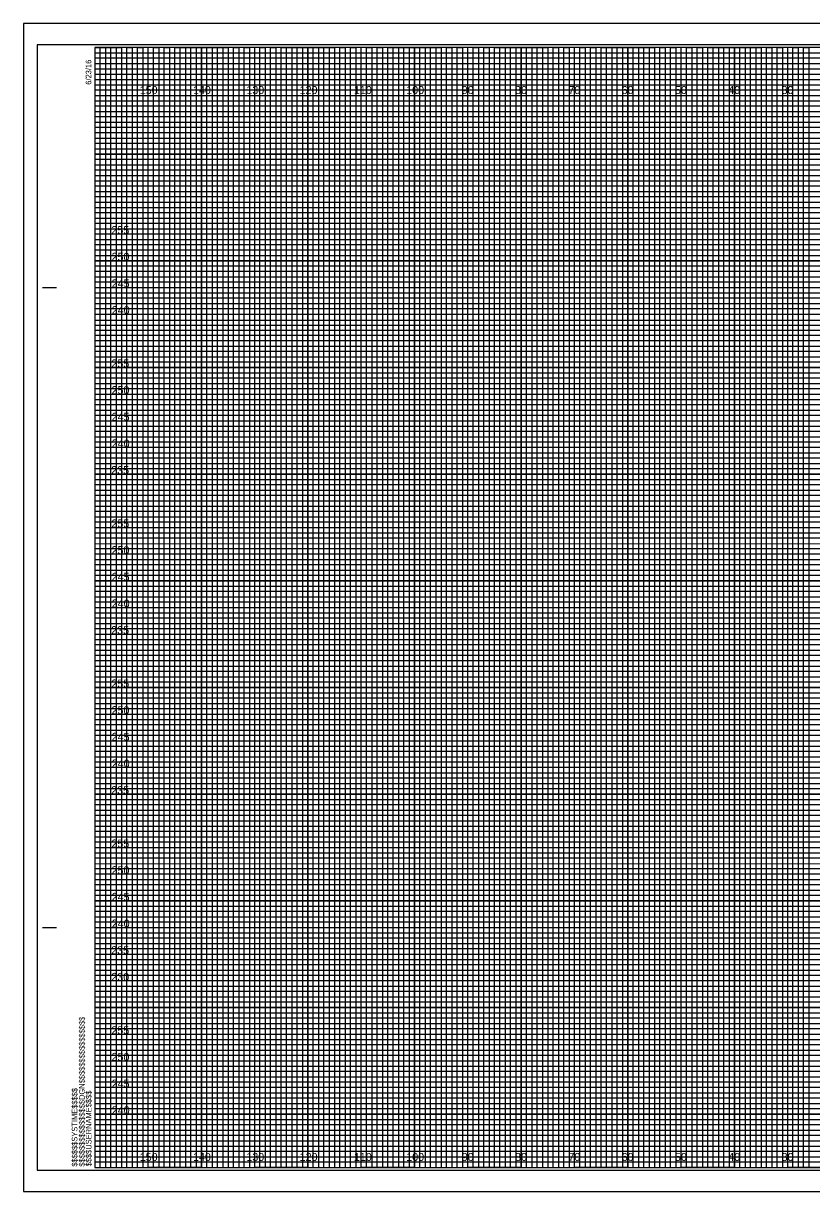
# Model space of a CAD drawing. Extents: x -13 to 323, y -5 to 434.
# Drawn here: x -13.4 to 134.5, y -4.5 to 214.5 of the extents above; entities that cross this region are included whole.
import ezdxf

# ---------------------------------------------------------------- set-up
doc = ezdxf.new("R2010")
doc.units = 0
for name, color, linetype in [('Exist Cross Section Cell', 7, 'Continuous'), ('Exist XS Center Line Elevation Label', 7, 'Continuous'), ('Exist XS Ground Line', 7, 'Continuous'), ('Prop CMT Conc Surface', 7, 'Continuous'), ('Prop CMT Concrete Structures', 7, 'Continuous'), ('Prop CMT DNC', 7, 'Continuous'), ('Prop CMT Pvmt Course 1 Wedge', 7, 'Continuous'), ('Prop CMT Pvmt Course 2', 7, 'Continuous'), ('Prop CMT Pvmt Course 2 Wedge', 7, 'Continuous'), ('Prop CMT Pvmt Course 3', 7, 'Continuous'), ('Prop CMT Subgrade Earthwork', 7, 'Continuous')]:
    doc.layers.add(name, color=color, linetype=linetype)

msp = doc.modelspace()

# ---------------------------------------------------------------- linework, layer by layer
at = {"layer": 'Exist XS Center Line Elevation Label'}
for points in [[(0, 210), (5, 210), (5, 0), (15, 0), (15, 210), (25, 210), (25, 0), (35, 0), (35, 210), (45, 210), (45, 0), (55, 0), (55, 210), (65, 210), (65, 0), (75, 0), (75, 210), (85, 210), (85, 0), (95, 0), (95, 210), (105, 210), (105, 0), (115, 0), (115, 210), (125, 210), (125, 0), (135, 0)], [(0, 205), (275, 205)], [(0, 185), (320, 185), (320, 195), (0, 195)], [(0, 165), (320, 165), (320, 175), (0, 175)], [(0, 145), (320, 145), (320, 155), (0, 155)], [(0, 125), (320, 125), (320, 135), (0, 135)], [(0, 105), (320, 105), (320, 115), (0, 115)], [(0, 85), (320, 85), (320, 95), (0, 95)], [(0, 65), (320, 65), (320, 75), (0, 75)], [(0, 45), (320, 45), (320, 55), (0, 55)], [(0, 25), (320, 25), (320, 35), (0, 35)], [(0, 5), (320, 5), (320, 15), (0, 15)]]:
    msp.add_lwpolyline(points, dxfattribs=at)
at = {"layer": 'Exist XS Ground Line'}
for p, q in [((10, 210), (0, 210)), ((10, 0), (10, 210)), ((30, 210), (20, 210)), ((20, 210), (20, 0)), ((30, 0), (30, 210)), ((50, 210), (40, 210)), ((40, 210), (40, 0)), ((50, 0), (50, 210)), ((70, 210), (60, 210)), ((60, 210), (60, 0)), ((70, 0), (70, 210)), ((90, 210), (80, 210)), ((80, 210), (80, 0)), ((90, 0), (90, 210)), ((110, 210), (100, 210)), ((100, 210), (100, 0)), ((110, 0), (110, 210)), ((130, 210), (120, 210)), ((120, 210), (120, 0)), ((130, 0), (130, 210)), ((20, 0), (10, 0)), ((40, 0), (30, 0)), ((60, 0), (50, 0)), ((80, 0), (70, 0)), ((100, 0), (90, 0)), ((120, 0), (110, 0)), ((140, 0), (130, 0))]:
    msp.add_line(p, q, dxfattribs=at)
for points in [[(0, 200), (320, 200), (320, 190), (0, 190)], [(0, 180), (320, 180), (320, 170), (0, 170)], [(0, 160), (320, 160), (320, 150), (0, 150)], [(0, 140), (320, 140), (320, 130), (0, 130)], [(0, 120), (320, 120), (320, 110), (0, 110)], [(0, 100), (320, 100), (320, 90), (0, 90)], [(0, 80), (320, 80), (320, 70), (0, 70)], [(0, 60), (320, 60), (320, 50), (0, 50)], [(0, 40), (320, 40), (320, 30), (0, 30)], [(0, 20), (320, 20), (320, 10), (0, 10)]]:
    msp.add_lwpolyline(points, dxfattribs=at)
at = {"layer": 'Prop CMT Conc Surface'}
msp.add_lwpolyline([(-13.4, -4.5), (323.3, -4.5), (323.3, 214.5), (-13.4, 214.5)], close=True, dxfattribs=at)
at = {"layer": 'Prop CMT Concrete Structures'}
for p, q in [((-9.8, 165), (-7.3, 165)), ((-9.7, 165), (-7.2, 165)), ((-9.8, 45), (-7.3, 45)), ((-9.7, 45), (-7.2, 45)), ((0, 0), (0, 0)), ((0, 0), (0, 0)), ((0, 0), (0, 0)), ((0, 0), (0, 0)), ((0, 0), (0, 0)), ((0, 0), (0, 0)), ((0, 0), (0, 0))]:
    msp.add_line(p, q, dxfattribs=at)
msp.add_lwpolyline([(320, 210), (0, 210), (0, 0), (320, 0)], close=True, dxfattribs=at)
at = {"layer": 'Prop CMT DNC'}
for points in [[(0, 0), (1, 0), (1, 210), (2, 210), (2, 0)], [(2, 0), (3, 0), (3, 210), (4, 210), (4, 0)], [(5, 0), (6, 0), (6, 210), (7, 210), (7, 0)], [(7, 0), (8, 0), (8, 210), (9, 210), (9, 0)], [(10, 0), (11, 0), (11, 210), (12, 210), (12, 0)], [(12, 0), (13, 0), (13, 210), (14, 210), (14, 0)], [(15, 0), (16, 0), (16, 210), (17, 210), (17, 0)], [(17, 0), (18, 0), (18, 210), (19, 210), (19, 0)], [(20, 0), (21, 0), (21, 210), (22, 210), (22, 0)], [(22, 0), (23, 0), (23, 210), (24, 210), (24, 0)], [(25, 0), (26, 0), (26, 210), (27, 210), (27, 0)], [(27, 0), (28, 0), (28, 210), (29, 210), (29, 0)], [(30, 0), (31, 0), (31, 210), (32, 210), (32, 0)], [(32, 0), (33, 0), (33, 210), (34, 210), (34, 0)], [(35, 0), (36, 0), (36, 210), (37, 210), (37, 0)], [(37, 0), (38, 0), (38, 210), (39, 210), (39, 0)], [(40, 0), (41, 0), (41, 210), (42, 210), (42, 0)], [(42, 0), (43, 0), (43, 210), (44, 210), (44, 0)], [(45, 0), (46, 0), (46, 210), (47, 210), (47, 0)], [(47, 0), (48, 0), (48, 210), (49, 210), (49, 0)], [(50, 0), (51, 0), (51, 210), (52, 210), (52, 0)], [(52, 0), (53, 0), (53, 210), (54, 210), (54, 0)], [(55, 0), (56, 0), (56, 210), (57, 210), (57, 0)], [(57, 0), (58, 0), (58, 210), (59, 210), (59, 0)], [(60, 0), (61, 0), (61, 210), (62, 210), (62, 0)], [(62, 0), (63, 0), (63, 210), (64, 210), (64, 0)], [(65, 0), (66, 0), (66, 210), (67, 210), (67, 0)], [(67, 0), (68, 0), (68, 210), (69, 210), (69, 0)], [(70, 0), (71, 0), (71, 210), (72, 210), (72, 0)], [(72, 0), (73, 0), (73, 210), (74, 210), (74, 0)], [(75, 0), (76, 0), (76, 210), (77, 210), (77, 0)], [(77, 0), (78, 0), (78, 210), (79, 210), (79, 0)], [(80, 0), (81, 0), (81, 210), (82, 210), (82, 0)], [(82, 0), (83, 0), (83, 210), (84, 210), (84, 0)], [(85, 0), (86, 0), (86, 210), (87, 210), (87, 0)], [(87, 0), (88, 0), (88, 210), (89, 210), (89, 0)], [(90, 0), (91, 0), (91, 210), (92, 210), (92, 0)], [(92, 0), (93, 0), (93, 210), (94, 210), (94, 0)], [(95, 0), (96, 0), (96, 210), (97, 210), (97, 0)], [(97, 0), (98, 0), (98, 210), (99, 210), (99, 0)], [(100, 0), (101, 0), (101, 210), (102, 210), (102, 0)], [(102, 0), (103, 0), (103, 210), (104, 210), (104, 0)], [(105, 0), (106, 0), (106, 210), (107, 210), (107, 0)], [(107, 0), (108, 0), (108, 210), (109, 210), (109, 0)], [(110, 0), (111, 0), (111, 210), (112, 210), (112, 0)], [(112, 0), (113, 0), (113, 210), (114, 210), (114, 0)], [(115, 0), (116, 0), (116, 210), (117, 210), (117, 0)], [(117, 0), (118, 0), (118, 210), (119, 210), (119, 0)], [(120, 0), (121, 0), (121, 210), (122, 210), (122, 0)], [(122, 0), (123, 0), (123, 210), (124, 210), (124, 0)], [(125, 0), (126, 0), (126, 210), (127, 210), (127, 0)], [(127, 0), (128, 0), (128, 210), (129, 210), (129, 0)], [(130, 0), (131, 0), (131, 210), (132, 210), (132, 0)], [(132, 0), (133, 0), (133, 210), (134, 210), (134, 0)]]:
    msp.add_lwpolyline(points, dxfattribs=at)
at = {"layer": 'Prop CMT Pvmt Course 1 Wedge'}
for p, q in [((323.3, 214.5), (-13.4, 214.5)), ((-13.4, 214.5), (-13.4, -4.5)), ((-13.4, -4.5), (323.3, -4.5))]:
    msp.add_line(p, q, dxfattribs=at)
at = {"layer": 'Prop CMT Pvmt Course 2'}
msp.add_lwpolyline([(-10.8, -0.5), (322.4, -0.5), (322.4, 210.5), (-10.8, 210.5)], close=True, dxfattribs=at)
at = {"layer": 'Prop CMT Pvmt Course 3'}
for p, q in [((10, 0), (10, 210)), ((20, 0), (20, 210)), ((30, 0), (30, 210)), ((40, 0), (40, 210)), ((50, 0), (50, 210)), ((60, 0), (60, 210)), ((70, 0), (70, 210)), ((80, 0), (80, 210)), ((90, 0), (90, 210)), ((100, 0), (100, 210)), ((110, 0), (110, 210)), ((120, 0), (120, 210)), ((130, 0), (130, 210)), ((0, 200), (320, 200)), ((0, 190), (320, 190)), ((0, 180), (320, 180)), ((0, 170), (320, 170)), ((0, 160), (320, 160)), ((0, 150), (320, 150)), ((0, 140), (320, 140)), ((0, 130), (320, 130)), ((0, 120), (320, 120)), ((0, 110), (320, 110)), ((0, 100), (320, 100)), ((0, 90), (320, 90)), ((0, 80), (320, 80)), ((0, 70), (320, 70)), ((0, 60), (320, 60)), ((0, 50), (320, 50)), ((0, 40), (320, 40)), ((0, 30), (320, 30)), ((0, 20), (320, 20)), ((0, 10), (320, 10))]:
    msp.add_line(p, q, dxfattribs=at)
at = {"layer": 'Prop CMT Subgrade Earthwork'}
for p, q in [((0, 209), (260, 209)), ((260, 207.98), (0, 207.98)), ((0, 207.98), (0, 207)), ((0, 207), (260, 207)), ((260, 205.89), (0, 205.89)), ((0, 205.89), (0, 204)), ((0, 204), (320, 204))]:
    msp.add_line(p, q, dxfattribs=at)
for points in [[(0, 203), (270, 203), (320, 203), (320, 202), (0, 202)], [(0, 201), (320, 201), (320, 199), (0, 199)], [(0, 198), (320, 198), (320, 197), (0, 196.98)], [(0, 196), (320, 196), (320, 194), (0, 194)], [(0, 193), (320, 193), (320, 192), (0, 192)], [(0, 191), (320, 191), (320, 189), (0, 189)], [(0, 188), (320, 188), (320, 187), (0, 187)], [(0, 186), (320, 186), (320, 184), (0, 184)], [(0, 183), (320, 183), (320, 182), (0, 182)], [(0, 181), (320, 181), (320, 179), (0, 179)], [(0, 178), (320, 178), (320, 177), (0, 177)], [(0, 176), (320, 176), (320, 173.95), (320, 173), (320, 172), (0, 172)], [(0, 174), (320, 174), (320, 173), (0, 173)], [(0, 171), (320, 171), (320, 169), (0, 169.03)], [(0, 169.03), (320, 169), (320, 168), (0, 168)], [(0, 167), (320, 167), (320, 166), (0, 166)], [(0, 164), (320, 164), (320, 163), (0, 163)], [(0, 162), (320, 162), (320, 161), (0, 161)], [(-0.07, 158.89), (320, 158.89), (320, 157.88), (-0.07, 157.88)], [(0, 157), (320, 157), (320, 156), (0, 156)], [(0, 154), (320, 154), (320, 153), (0, 153)], [(0, 152), (320, 152), (320, 151), (0, 151)], [(0, 149), (320, 149), (320, 148), (0, 148)], [(0, 147), (320, 147), (320, 146), (0, 146)], [(0, 144), (320, 144), (320, 143), (0, 143)], [(0, 142), (320, 142), (320, 141), (0, 141)], [(0, 139), (320, 139), (319.99, 137.98), (0, 138)], [(0, 137), (320, 137), (320, 136), (0, 136)], [(0, 134), (320, 134), (320, 133), (0, 133)], [(0, 132), (320, 132), (320, 131), (0, 131)], [(0, 129), (320, 129), (320, 128), (0, 128)], [(0, 127), (320, 127), (320, 126), (0, 126)], [(0, 124), (320, 124), (320, 123), (0, 123)], [(0, 122), (320, 122), (320, 121), (0, 121)], [(0, 119), (320, 119), (320, 118), (0, 118)], [(0, 116.99), (320.07, 116.91), (320, 116), (0, 116)], [(0, 114), (320, 114), (320, 113), (0, 113)], [(0, 112), (320, 112), (320, 111), (0, 111)], [(0, 109), (320, 109), (320, 108), (0, 108)], [(0, 107), (320, 107), (320, 106), (0, 106)], [(0, 104), (320, 104), (320, 103), (0, 103)], [(0, 102), (320, 102), (320, 101), (0, 101)], [(0, 99), (320, 99), (320, 98), (0, 98)], [(0, 97), (320, 97), (320, 96), (0, 96)], [(0, 94), (320, 94), (320, 93), (0, 93)], [(0, 92), (320, 92), (320, 91), (0, 91)], [(0, 89), (320, 89), (320, 88), (0, 88)], [(0, 87), (320, 87), (320, 86), (0, 86)], [(0, 84), (320, 84), (320, 83), (0, 83)], [(0, 82), (320, 82), (320, 81), (0, 81)], [(0, 79), (320, 79), (319.99, 77.98), (0, 78)], [(0, 77), (320, 77), (320, 76), (0, 76)], [(0, 74), (320, 74), (320, 73), (0, 73)], [(0, 72), (320, 72), (320, 71), (0, 71)], [(0, 69), (320, 69), (320, 68), (0, 68)], [(0, 67), (320, 67), (320, 66), (0, 66)], [(0, 64), (320, 64), (320, 63), (0, 63)], [(0, 62), (320, 62), (320, 61), (0, 61)], [(0, 59), (320, 59), (320, 58), (0, 58)], [(0, 56.99), (320.07, 56.91), (320, 56), (0, 56)], [(0, 54), (320, 54), (320, 53), (0, 53)], [(0, 52), (320, 52), (320, 51), (0, 51)], [(0, 49), (320, 49), (320, 48), (0, 48)], [(0, 47), (320, 47), (320, 46), (0, 46)], [(0, 44), (320, 44), (320, 43), (0, 43)], [(0, 42), (320, 42), (320, 41), (0, 41)], [(0, 39), (320, 39), (320, 38), (0, 38)], [(0, 37), (320, 37), (320, 36), (0, 36)], [(0, 34), (320, 34), (320, 33), (0, 33)], [(0, 32), (320, 32), (320, 31), (0, 31)], [(0, 29), (320, 29), (320, 28), (0, 28)], [(0, 27), (320, 27), (320, 26), (0, 26)], [(0, 24), (320, 24), (320, 23), (0, 23)], [(0, 22), (320, 22), (320, 21), (0, 21)], [(0, 19), (320, 19), (320, 18), (0, 18)], [(0, 17), (320, 17), (320, 16), (0, 16)], [(0, 14), (320, 14), (320, 13), (0, 13)], [(0, 12), (320, 12), (320, 11), (0, 11)], [(0, 9), (320, 9), (320, 8), (0, 8)], [(0, 7), (320, 7), (320, 6), (0, 6)], [(0, 4), (320, 4), (320, 3), (0, 3)], [(0, 2), (320, 2), (320, 1), (0, 1)]]:
    msp.add_lwpolyline(points, dxfattribs=at)

# ---------------------------------------------------------------- texts
at = {"layer": 'Exist Cross Section Cell'}
for s, p in [('150', (8.44, 201.25)), ('140', (18.44, 201.25)), ('130', (28.44, 201.25)), ('120', (38.44, 201.25)), ('110', (48.62, 201.25)), ('100', (58.44, 201.25)), ('90', (68.86, 201.25)), ('80', (78.86, 201.25)), ('70', (88.86, 201.25)), ('60', (98.86, 201.25)), ('50', (108.86, 201.25)), ('40', (118.86, 201.25)), ('30', (128.86, 201.25)), ('150', (8.44, 1.25)), ('140', (18.44, 1.25)), ('130', (28.44, 1.25)), ('120', (38.44, 1.25)), ('110', (48.62, 1.25)), ('100', (58.44, 1.25)), ('90', (68.86, 1.25)), ('80', (78.86, 1.25)), ('70', (88.86, 1.25)), ('60', (98.86, 1.25)), ('50', (108.86, 1.25)), ('40', (118.86, 1.25)), ('30', (128.86, 1.25))]:
    msp.add_text(s, height=1.5, dxfattribs=at).set_placement(p)
at = {"layer": 'Prop CMT Concrete Structures'}
for s, p in [('6/23/16', (-0.65, 203)), ('$$$$$$$$$$$$$$$$DGN$$$$$$$$$$$$$$$$', (-1.88, 0.18)), ('$$$$$$SYSTIME$$$$$', (-3.26, 0.18)), ('$$$$USERNAME$$$$', (-0.62, 0.23))]:
    msp.add_text(s, height=1.05, rotation=90, dxfattribs=at).set_placement(p)
at = {"layer": 'Prop CMT Pvmt Course 2 Wedge'}
for s, p in [('255', (3.13, 175)), ('250', (3.15, 170)), ('245', (3.18, 165)), ('240', (3.19, 160)), ('255', (3.13, 150)), ('250', (3.15, 145)), ('245', (3.18, 140)), ('240', (3.19, 135)), ('235', (3.09, 130)), ('255', (3.13, 120)), ('250', (3.15, 115)), ('245', (3.18, 110)), ('240', (3.19, 105)), ('235', (3.09, 100)), ('255', (3.13, 90)), ('250', (3.15, 85)), ('245', (3.18, 80)), ('240', (3.19, 75)), ('235', (3.09, 70)), ('255', (3.13, 60)), ('250', (3.15, 55)), ('245', (3.18, 50)), ('240', (3.19, 45)), ('235', (3.09, 40)), ('230', (3.11, 35)), ('255', (3.13, 25)), ('250', (3.15, 20)), ('245', (3.18, 15)), ('240', (3.19, 10))]:
    msp.add_text(s, height=1.5, dxfattribs=at).set_placement(p)

doc.saveas('drawing.dxf')
